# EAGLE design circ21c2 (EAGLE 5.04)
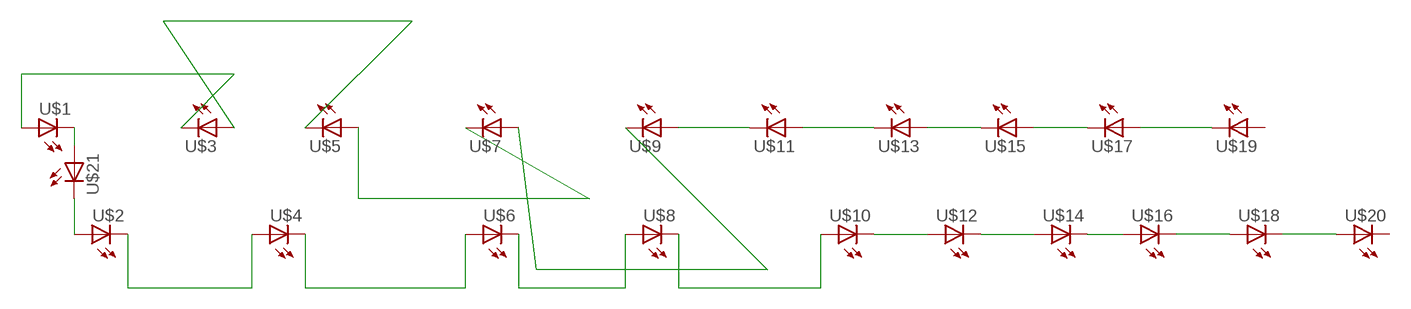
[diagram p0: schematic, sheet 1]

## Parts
U$1  LED5MM  [LED5MM]
U$2  LED5MM  [LED5MM]
U$3  LED5MM  [LED5MM]
U$4  LED5MM  [LED5MM]
U$5  LED5MM  [LED5MM]
U$6  LED5MM  [LED5MM]
U$7  LED5MM  [LED5MM]
U$8  LED5MM  [LED5MM]
U$9  LED5MM  [LED5MM]
U$10  LED5MM  [LED5MM]
U$11  LED5MM  [LED5MM]
U$12  LED5MM  [LED5MM]
U$13  LED5MM  [LED5MM]
U$14  LED5MM  [LED5MM]
U$15  LED5MM  [LED5MM]
U$16  LED5MM  [LED5MM]
U$17  LED5MM  [LED5MM]
U$18  LED5MM  [LED5MM]
U$19  LED5MM  [LED5MM]
U$20  LED5MM  [LED5MM]
U$21  LED5MM  [LED5MM]

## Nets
N$1: U$1.K(C) U$21.A
N$2: U$2.K(C) U$4.A
N$3: U$4.K(C) U$6.A
N$4: U$6.K(C) U$8.A
N$5: U$8.K(C) U$10.A
N$6: U$1.A U$3.K(C)
N$7: U$3.A U$5.K(C)
N$8: U$5.A U$7.K(C)
N$9: U$7.A U$9.K(C)
N$10: U$2.A U$21.K(C)
N$11: U$9.A U$11.K(C)
N$12: U$11.A U$13.K(C)
N$13: U$13.A U$15.K(C)
N$14: U$15.A U$17.K(C)
N$15: U$10.K(C) U$12.A
N$16: U$12.K(C) U$14.A
N$17: U$14.K(C) U$16.A
N$18: U$17.A U$19.K(C)
N$19: U$16.K(C) U$18.A
N$20: U$18.K(C) U$20.A
Unconnected: U$19.A U$20.K(C)

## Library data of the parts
U$1-U$21 = led(2):LED: LED

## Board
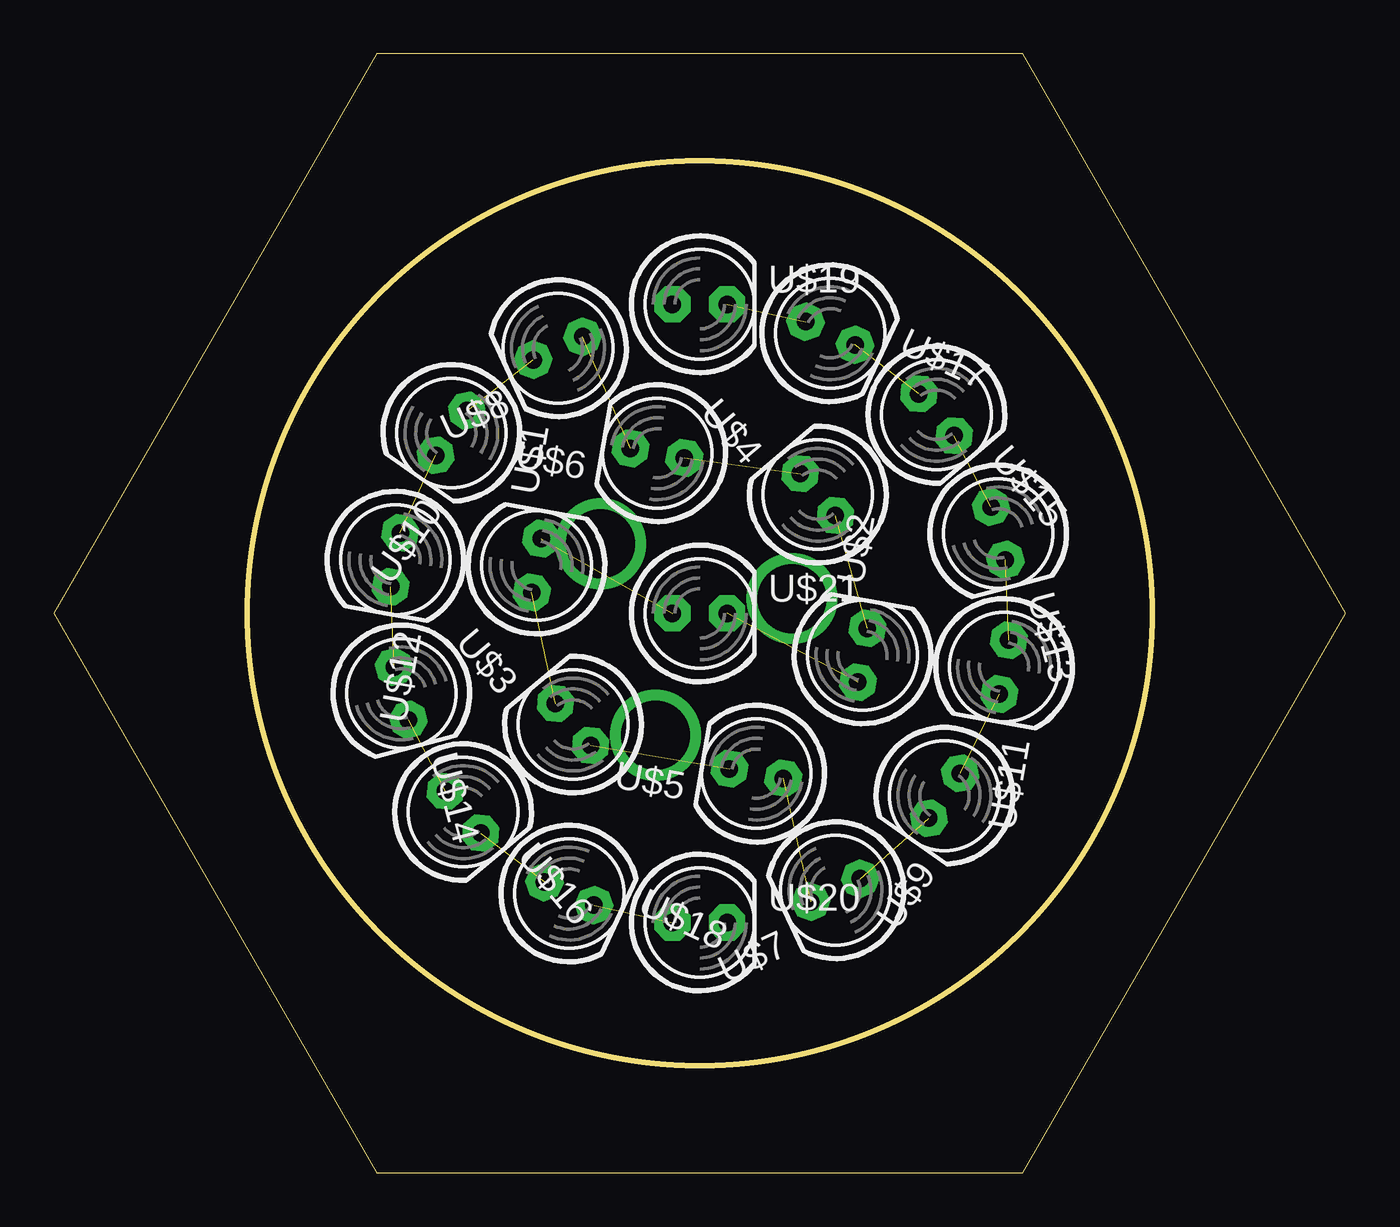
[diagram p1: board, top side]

Size 60 x 51.96 mm. Coordinates in mm from the lower left corner, seen from the top.
Outline: 15,0 45,0 60,25.98 45,51.96 15,51.96 0,25.98 15,0
Outline: circle at 30,25.98 radius 21
Copper layers (1*16): Top 0.035mm / dielectric 1.5mm / Bottom 0.035mm
Design rules "default": minimum track width 10mil, minimum drill 24mil, track to track 8mil, track to pad 8mil, pad to pad 8mil, via to via 8mil, smd to smd 8mil, copper to edge 40mil, drill to drill 8mil, minimum pad ring 10mil, minimum via ring 8mil, stop-mask expansion 4mil, vias tented up to drill 0mil, thermal gap 10mil

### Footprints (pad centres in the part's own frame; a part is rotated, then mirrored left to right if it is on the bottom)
LED5MM = drill 0.813 pad 1.676 octagon: A -1.27,0; K 1.27,0

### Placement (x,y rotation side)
U$1  22.42,28.2 80 top
U$2  37.56,24.04 80 top
U$3  24.11,20.82 130 top
U$4  35.49,31.5 130 top
U$5  32.63,18.54 170 top
U$6  28.03,33.42 170 top
U$7  36.3,13.13 205 top
U$8  23.42,38.29 205 top
U$9  41.37,17.52 235 top
U$10  18.46,34.36 235 top
U$11  44.13,23.49 260 top
U$12  15.87,28.47 260 top
U$13  43.86,29.69 285 top
U$14  16.14,22.27 285 top
U$15  40.99,35.2 310 top
U$16  19.01,16.76 310 top
U$17  36.06,38.99 335 top
U$18  23.93,12.97 335 top
U$19  30,40.33 0 top
U$20  30,11.63 0 top
U$21  30,25.98 0 top

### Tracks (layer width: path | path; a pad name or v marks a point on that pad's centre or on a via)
N$1  (1 unrouted)
N$2  (1 unrouted)
N$3  (1 unrouted)
N$4  (1 unrouted)
N$5  (1 unrouted)
N$6  (1 unrouted)
N$7  (1 unrouted)
N$8  (1 unrouted)
N$9  (1 unrouted)
N$10  (1 unrouted)
N$11  (1 unrouted)
N$12  (1 unrouted)
N$13  (1 unrouted)
N$14  (1 unrouted)
N$15  (1 unrouted)
N$16  (1 unrouted)
N$17  (1 unrouted)
N$18  (1 unrouted)
N$19  (1 unrouted)
N$20  (1 unrouted)
N$21  (via drill 3.2)
  other vias: 27.94,20.32
N$22  (via drill 3.2)
  other vias: 34.29,26.67
N$23  (via drill 3.2)
  other vias: 25.4,29.21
